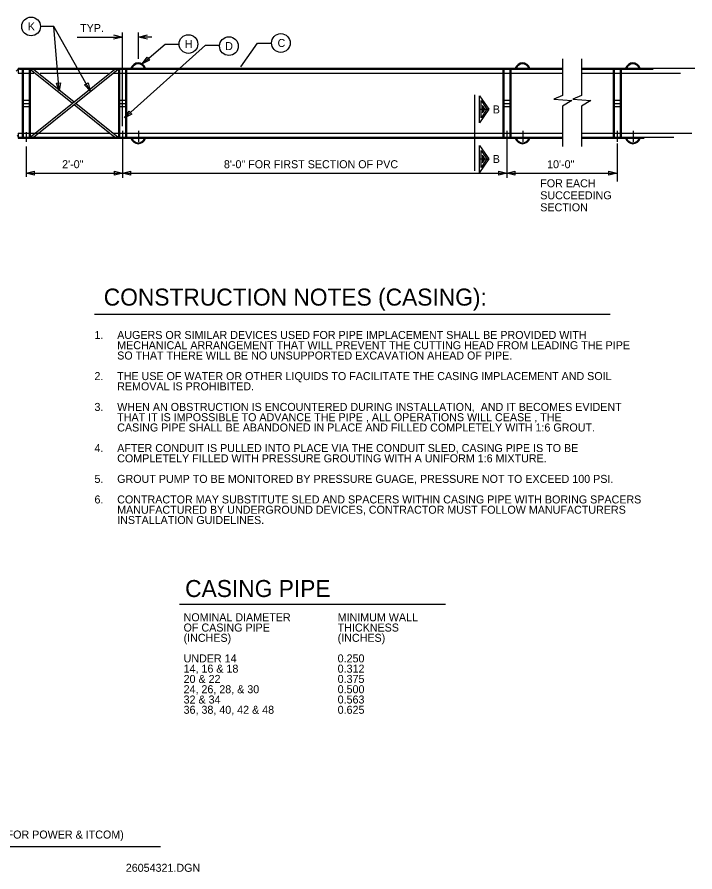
# Model space of a CAD drawing. Extents: x 10068 to 10200, y 10013 to 10177.
# Drawn here: x 10142.3 to 10198.7, y 10012.6 to 10083.8 of the extents above; entities that cross this region are included whole.
import ezdxf

# ---------------------------------------------------------------- set-up
doc = ezdxf.new("R2010")
doc.units = 0
for name, color, linetype in [('Level 3', 7, 'Continuous'), ('Level 40', 7, 'Continuous'), ('Level 52', 7, 'Continuous'), ('Level 60', 7, 'Continuous'), ('Level 62', 7, 'Continuous'), ('Level 63', 7, 'Continuous')]:
    doc.layers.add(name, color=color, linetype=linetype)

msp = doc.modelspace()

# ---------------------------------------------------------------- linework, layer by layer
at = {"layer": 'Level 40'}
msp.add_line((10180.387, 10077.348), (10180.387, 10071.014), dxfattribs=at)
for points in [[(10180.811, 10077.274), (10181.561, 10076.149), (10180.811, 10075.024), (10180.811, 10077.274)], [(10180.936, 10076.861), (10181.411, 10076.149), (10180.936, 10075.437), (10180.936, 10076.861)], [(10180.811, 10076.149), (10181.561, 10076.149)], [(10181.061, 10076.461), (10181.061, 10075.836), (10181.248, 10076.149), (10181.061, 10076.461)], [(10180.811, 10073.125), (10181.561, 10072), (10180.811, 10070.875), (10180.811, 10073.125)], [(10180.936, 10072.712), (10181.411, 10072), (10180.936, 10071.288), (10180.936, 10072.712)], [(10181.061, 10072.313), (10181.061, 10071.688), (10181.248, 10072), (10181.061, 10072.313)], [(10180.811, 10072), (10181.561, 10072)]]:
    msp.add_lwpolyline(points, dxfattribs=at)
at = {"layer": 'Level 52'}
msp.add_line((10114.36, 10014.738), (10154.23, 10014.738), dxfattribs=at)
at = {"layer": 'Level 60'}
for p, q in [((10142.398, 10079.556), (10142.398, 10079.14)), ((10142.731, 10079.473), (10142.731, 10073.806)), ((10142.814, 10079.473), (10142.814, 10073.806)), ((10143.314, 10079.473), (10143.314, 10073.806)), ((10150.814, 10079.473), (10150.814, 10073.806)), ((10151.314, 10079.473), (10151.314, 10073.805)), ((10182.814, 10079.473), (10182.814, 10073.806)), ((10183.314, 10079.473), (10183.314, 10073.805)), ((10191.998, 10079.473), (10191.998, 10073.806)), ((10192.498, 10079.473), (10192.498, 10073.805)), ((10142.398, 10079.14), (10142.702, 10079.14)), ((10142.76, 10079.14), (10143.357, 10079.14)), ((10150.749, 10079.14), (10151.387, 10079.14)), ((10142.731, 10076.61), (10143.399, 10076.61)), ((10150.731, 10076.61), (10151.399, 10076.61)), ((10182.731, 10076.61), (10183.399, 10076.61)), ((10191.915, 10076.61), (10192.583, 10076.61)), ((10142.398, 10074.14), (10143.398, 10074.14)), ((10142.398, 10074.14), (10142.398, 10073.723)), ((10150.758, 10074.14), (10151.378, 10074.14))]:
    msp.add_line(p, q, dxfattribs=at)
for points in [[(10142.815, 10076.888), (10143.315, 10076.888), (10143.315, 10076.347), (10142.815, 10076.347)], [(10150.815, 10076.888), (10151.315, 10076.888), (10151.315, 10076.347), (10150.815, 10076.347)], [(10182.815, 10076.888), (10183.315, 10076.888), (10183.315, 10076.347), (10182.815, 10076.347)], [(10191.999, 10076.888), (10192.499, 10076.888), (10192.499, 10076.347), (10191.999, 10076.347)]]:
    msp.add_lwpolyline(points, close=True, dxfattribs=at)
at = {"layer": 'Level 62'}
for p, q in [((10142.398, 10079.556), (10187.702, 10079.556)), ((10142.496, 10079.473), (10187.702, 10079.473)), ((10143.398, 10079.473), (10143.398, 10073.806)), ((10143.398, 10073.806), (10150.435, 10079.473)), ((10143.398, 10079.473), (10146.918, 10076.641)), ((10143.663, 10073.806), (10150.7, 10079.473)), ((10143.663, 10079.473), (10147.05, 10076.748)), ((10150.731, 10079.473), (10150.731, 10073.806)), ((10151.398, 10079.473), (10151.398, 10073.806)), ((10182.731, 10079.473), (10182.731, 10073.806)), ((10183.398, 10079.473), (10183.398, 10073.806)), ((10189.283, 10079.556), (10198.731, 10079.556)), ((10189.283, 10079.473), (10195.26, 10079.473)), ((10191.915, 10079.473), (10191.915, 10073.806)), ((10192.582, 10079.473), (10192.582, 10073.806)), ((10143.449, 10079.14), (10143.702, 10079.14)), ((10144.207, 10079.14), (10149.919, 10079.14)), ((10150.333, 10079.14), (10150.709, 10079.14)), ((10151.427, 10079.14), (10187.702, 10079.14)), ((10189.283, 10079.14), (10197.545, 10079.14)), ((10147.183, 10076.641), (10150.706, 10073.806)), ((10147.051, 10076.534), (10150.441, 10073.806)), ((10142.398, 10073.723), (10187.702, 10073.723)), ((10142.575, 10073.806), (10187.702, 10073.806)), ((10143.426, 10074.14), (10150.002, 10074.14)), ((10150.336, 10074.14), (10150.677, 10074.14)), ((10151.447, 10074.14), (10187.702, 10074.14)), ((10189.283, 10074.14), (10198.468, 10074.14)), ((10189.283, 10073.806), (10196.974, 10073.806)), ((10189.283, 10073.723), (10194.513, 10073.723)), ((10148.74, 10059.07), (10191.663, 10059.07)), ((10155.817, 10034.911), (10177.962, 10034.911))]:
    msp.add_line(p, q, dxfattribs=at)
for centre, radius, start, end in [((10142.496, 10079.14), 0.333, 90, 147.09476), ((10152.382, 10079.379), 0.629, 16.42696, 163.57304), ((10152.382, 10079.379), 0.545, 18.44642, 161.18929), ((10184.382, 10079.379), 0.629, 16.42696, 163.57304), ((10184.382, 10079.379), 0.545, 18.44642, 161.18929), ((10193.566, 10079.379), 0.629, 16.42696, 163.57304), ((10193.566, 10079.379), 0.545, 18.44642, 161.18929), ((10142.574, 10074.14), 0.333, 214.07688, 270), ((10152.382, 10073.904), 0.629, 196.72499, 343.27501), ((10152.382, 10073.904), 0.545, 198.81071, 341.55358), ((10184.382, 10073.904), 0.629, 196.72499, 343.27501), ((10184.382, 10073.904), 0.545, 198.81071, 341.55358), ((10193.566, 10073.904), 0.629, 196.72499, 343.27501), ((10193.566, 10073.904), 0.545, 198.81071, 341.55358)]:
    msp.add_arc(centre, radius, start, end, dxfattribs=at)
at = {"layer": 'Level 63'}
for p, q in [((10151.064, 10074.721), (10151.064, 10082.535)), ((10152.393, 10080.336), (10152.393, 10082.535)), ((10147.297, 10082.16), (10151.064, 10082.16)), ((10153.518, 10082.16), (10152.393, 10082.16)), ((10187.702, 10080.336), (10187.702, 10077.277)), ((10189.283, 10080.336), (10189.283, 10077.277)), ((10182.749, 10079.14), (10183.387, 10079.14)), ((10191.933, 10079.14), (10192.571, 10079.14)), ((10187.702, 10076.398), (10187.702, 10073.037)), ((10189.283, 10076.398), (10189.283, 10073.037)), ((10143.064, 10074.232), (10143.064, 10073.427)), ((10151.064, 10074.346), (10151.064, 10073.427)), ((10151.064, 10073.971), (10151.064, 10070.44)), ((10152.398, 10074.346), (10152.398, 10073.427)), ((10182.758, 10074.14), (10183.378, 10074.14)), ((10183.064, 10074.346), (10183.064, 10073.427)), ((10183.064, 10074.346), (10183.064, 10073.427)), ((10184.398, 10074.346), (10184.398, 10073.427)), ((10191.942, 10074.14), (10192.563, 10074.14)), ((10192.248, 10074.346), (10192.248, 10073.427)), ((10192.248, 10074.346), (10192.248, 10073.427)), ((10193.582, 10074.346), (10193.582, 10073.427)), ((10143.064, 10073.052), (10143.064, 10070.528)), ((10183.064, 10073.596), (10183.064, 10070.438)), ((10192.248, 10073.291), (10192.248, 10070.134)), ((10143.064, 10070.815), (10151.064, 10070.815)), ((10151.064, 10070.815), (10183.064, 10070.815)), ((10183.064, 10070.813), (10192.228, 10070.813))]:
    msp.add_line(p, q, dxfattribs=at)
for points in [[(10148.394, 10077.672), (10145.366, 10083.04), (10144.241, 10083.04)], [(10145.799, 10077.672), (10145.366, 10083.04), (10144.241, 10083.04)], [(10150.314, 10082.347), (10151.064, 10082.16), (10150.314, 10081.972)], [(10153.143, 10081.972), (10152.393, 10082.16), (10153.143, 10082.347)], [(10152.72, 10079.923), (10154.623, 10081.568), (10155.748, 10081.568)], [(10160.939, 10079.663), (10162.323, 10081.655), (10163.448, 10081.655)], [(10151.249, 10075.421), (10157.997, 10081.482), (10159.122, 10081.482)], [(10187.702, 10077.277), (10186.998, 10076.97), (10188.492, 10076.882), (10187.702, 10076.398)], [(10189.283, 10077.277), (10188.58, 10076.97), (10190.074, 10076.882), (10189.283, 10076.398)]]:
    msp.add_lwpolyline(points, dxfattribs=at)
for points in [[(10153.333, 10080.233), (10152.72, 10079.923), (10153.115, 10080.485)], [(10153.333, 10080.233), (10152.72, 10079.923), (10153.115, 10080.485)], [(10145.911, 10078.35), (10145.799, 10077.672), (10145.579, 10078.323)], [(10148.212, 10078.335), (10148.394, 10077.672), (10147.921, 10078.171)], [(10151.856, 10075.743), (10151.249, 10075.421), (10151.634, 10075.991)], [(10143.731, 10070.648), (10143.064, 10070.815), (10143.731, 10070.982)], [(10150.398, 10070.982), (10151.064, 10070.815), (10150.398, 10070.648)], [(10151.731, 10070.648), (10151.064, 10070.815), (10151.731, 10070.982)], [(10182.398, 10070.982), (10183.064, 10070.815), (10182.398, 10070.648)], [(10183.731, 10070.647), (10183.064, 10070.813), (10183.731, 10070.98)], [(10191.561, 10070.98), (10192.228, 10070.813), (10191.561, 10070.647)]]:
    msp.add_lwpolyline(points, close=True, dxfattribs=at)
for centre in [(10143.462, 10083.04), (10156.56, 10081.576), (10164.26, 10081.663), (10159.935, 10081.403)]:
    msp.add_circle(centre, 0.779, dxfattribs=at)

# ---------------------------------------------------------------- texts
at = {"layer": 'Level 3'}
msp.add_text('26054321.DGN', height=0.66667, dxfattribs=at).set_placement((10151.347, 10012.631))
at = {"layer": 'Level 52'}
msp.add_text('(TYPICAL FOR POWER & ITCOM)', height=0.66667, dxfattribs=at).set_placement((10137.164, 10015.399))
at = {"layer": 'Level 62'}
for s, p in [('CONSTRUCTION NOTES (CASING):', (10149.514, 10059.789)), ('CASING PIPE', (10156.289, 10035.516))]:
    msp.add_text(s, height=1.41667, dxfattribs=at).set_placement(p)
at = {"layer": 'Level 63'}
for s, height, p in [('K', 0.667, (10143.192, 10082.707)), (' TYP.', 0.6667, (10147.297, 10082.577)), ('H', 0.667, (10156.251, 10081.243)), ('D', 0.667, (10159.624, 10081.07)), ('C', 0.667, (10163.985, 10081.329)), ('B', 0.667, (10181.901, 10075.8)), ('B', 0.667, (10181.901, 10071.667)), ('2\'-0"', 0.6667, (10146.048, 10071.232)), ('8\'-0" FOR FIRST SECTION OF PVC', 0.66667, (10159.517, 10071.232)), ('10\'-0"', 0.6667, (10186.426, 10071.23)), ('FOR EACH ', 0.6667, (10185.856, 10069.643)), ('SUCCEEDING ', 0.66667, (10185.856, 10068.643)), ('SECTION', 0.6667, (10185.856, 10067.643)), ('1.', 0.6667, (10148.74, 10057.011)), ('AUGERS OR SIMILAR DEVICES USED FOR PIPE IMPLACEMENT SHALL BE PROVIDED WITH ', 0.66667, (10150.632, 10057.011)), ('MECHANICAL ARRANGEMENT THAT WILL PREVENT THE CUTTING HEAD FROM LEADING THE PIPE', 0.66667, (10150.632, 10056.155)), ('SO THAT THERE WILL BE NO UNSUPPORTED EXCAVATION AHEAD OF PIPE.', 0.66667, (10150.632, 10055.299)), ('2.', 0.6667, (10148.74, 10053.586)), ('THE USE OF WATER OR OTHER LIQUIDS TO FACILITATE THE CASING IMPLACEMENT AND SOIL ', 0.66667, (10150.632, 10053.586)), ('REMOVAL IS PROHIBITED.', 0.66667, (10150.632, 10052.73)), ('3.', 0.6667, (10148.74, 10051.017)), ('WHEN AN OBSTRUCTION IS ENCOUNTERED DURING INSTALLATION,  AND IT BECOMES EVIDENT', 0.66667, (10150.632, 10051.017)), ('THAT IT IS IMPOSSIBLE TO ADVANCE THE PIPE , ALL OPERATIONS WILL CEASE , THE ', 0.66667, (10150.632, 10050.161)), ('CASING PIPE SHALL BE ABANDONED IN PLACE AND FILLED COMPLETELY WITH 1:6 GROUT.', 0.66667, (10150.632, 10049.305)), ('4.', 0.6667, (10148.74, 10047.592)), ('AFTER CONDUIT IS PULLED INTO PLACE VIA THE CONDUIT SLED, CASING PIPE IS TO BE ', 0.66667, (10150.632, 10047.592)), ('COMPLETELY FILLED WITH PRESSURE GROUTING WITH A UNIFORM 1:6 MIXTURE.', 0.66667, (10150.632, 10046.736)), ('5.', 0.6667, (10148.74, 10045.023)), ('GROUT PUMP TO BE MONITORED BY PRESSURE GUAGE, PRESSURE NOT TO EXCEED 100 PSI.', 0.66667, (10150.632, 10045.023)), ('6.', 0.6667, (10148.74, 10043.311)), ('CONTRACTOR MAY SUBSTITUTE SLED AND SPACERS WITHIN CASING PIPE WITH BORING SPACERS ', 0.66667, (10150.632, 10043.311)), ('MANUFACTURED BY UNDERGROUND DEVICES, CONTRACTOR MUST FOLLOW MANUFACTURERS ', 0.66667, (10150.632, 10042.454)), ('INSTALLATION GUIDELINES.', 0.66667, (10150.632, 10041.598)), ('NOMINAL DIAMETER', 0.66667, (10156.161, 10033.497)), ('MINIMUM WALL', 0.66667, (10168.987, 10033.497)), ('OF CASING PIPE', 0.66667, (10156.161, 10032.641)), ('THICKNESS', 0.6667, (10168.987, 10032.641)), ('(INCHES)', 0.6667, (10156.161, 10031.785)), ('(INCHES)', 0.6667, (10168.987, 10031.785)), ('UNDER 14', 0.6667, (10156.161, 10030.072)), ('0.250', 0.6667, (10168.987, 10030.072)), ('14, 16 & 18', 0.66667, (10156.161, 10029.216)), ('0.312', 0.6667, (10168.987, 10029.216)), ('20 & 22', 0.6667, (10156.161, 10028.36)), ('0.375', 0.6667, (10168.987, 10028.36)), ('24, 26, 28, & 30', 0.66667, (10156.161, 10027.503)), ('0.500', 0.6667, (10168.987, 10027.503)), ('32 & 34', 0.6667, (10156.161, 10026.647)), ('0.563', 0.6667, (10168.987, 10026.647)), ('36, 38, 40, 42 & 48', 0.66667, (10156.161, 10025.791)), ('0.625', 0.6667, (10168.987, 10025.791))]:
    msp.add_text(s, height=height, dxfattribs=at).set_placement(p)

doc.saveas('drawing.dxf')
